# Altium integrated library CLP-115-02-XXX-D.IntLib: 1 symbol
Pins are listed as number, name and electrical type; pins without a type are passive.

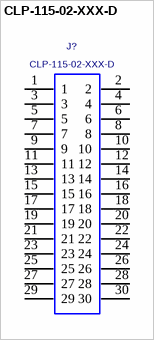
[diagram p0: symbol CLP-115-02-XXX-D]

## CLP-115-02-XXX-D
designator J?
LOW PROFILE .050 x .050 DOUBLE ROW ASM.; MANUFACTURER: SAMTEC
footprint CLP-115-02-XXX-D
pins: 1, 2, 3, 4, 5, 6, 7, 8, 9, 10, 11, 12, 13, 14, 15, 16, 17, 18, 19, 20, 21, 22, 23, 24, 25, 26, 27, 28, 29, 30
